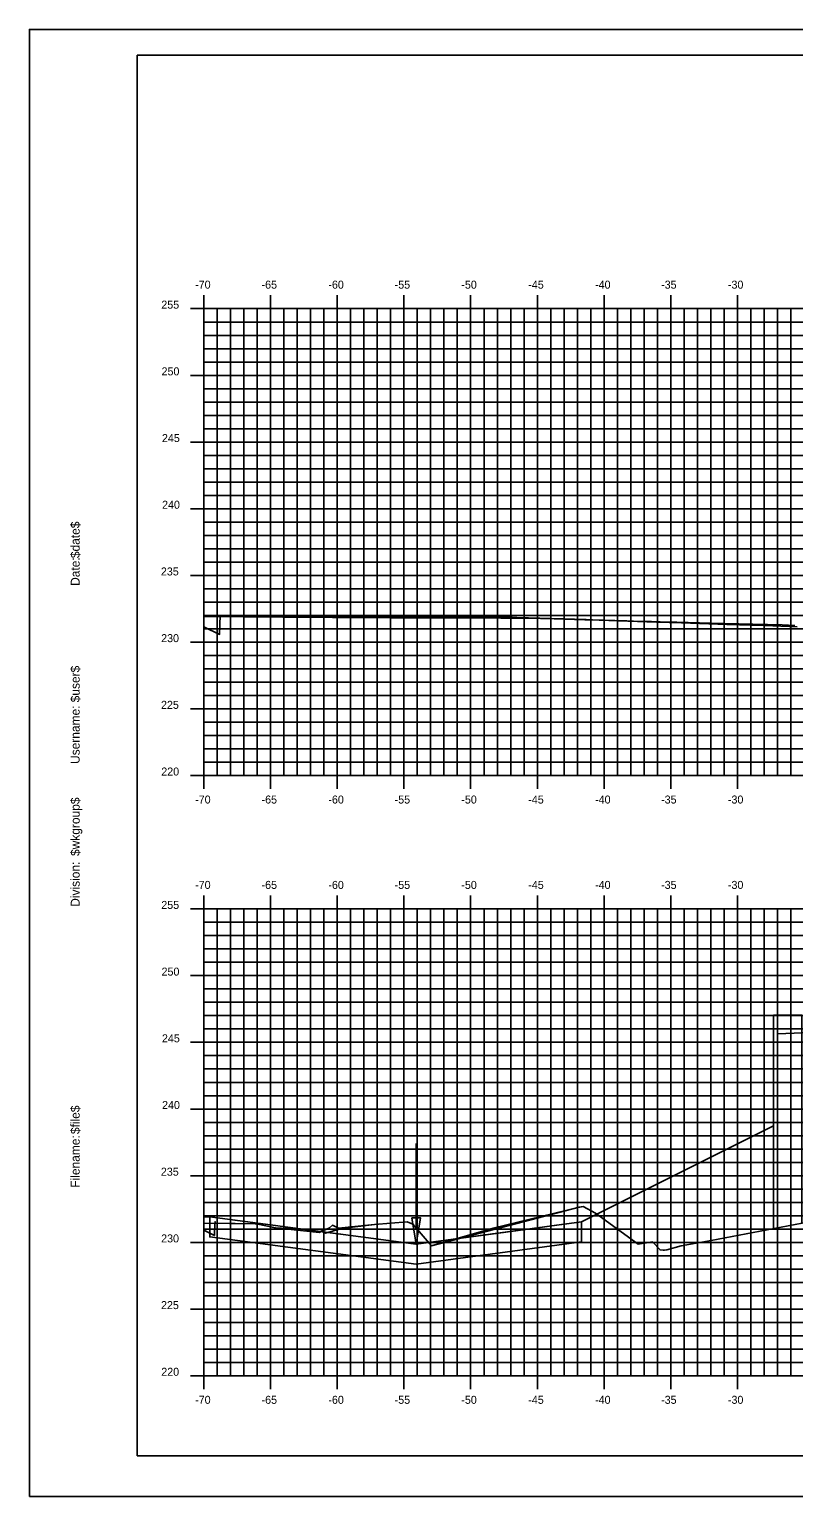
# Model space of a CAD drawing. Extents: x -22 to 1480, y -1511 to 8.
# Drawn here: x 548.6 to 605.9, y -1511.4 to -1401.4 of the extents above; entities that cross this region are included whole.
import ezdxf

# ---------------------------------------------------------------- set-up
doc = ezdxf.new("R2010")
doc.units = 0
for name, color, linetype in [('BORDER', 7, 'Continuous'), ('D_Bridge_Wingwall', 7, 'Continuous'), ('D_Drainage_Ditch_Line', 7, 'Continuous'), ('D_Roadway_Centerline', 7, 'Continuous'), ('D_Roadway_SlopeLines', 7, 'Continuous'), ('H_V ANNOTATION', 7, 'Continuous'), ('MAJOR', 7, 'Continuous'), ('MINOR', 7, 'Continuous'), ('PLOT BOUNDARY', 7, 'Continuous'), ('S_Roadway_Centerline', 7, 'Continuous')]:
    doc.layers.add(name, color=color, linetype=linetype)

msp = doc.modelspace()

# ---------------------------------------------------------------- linework, layer by layer
at = {"layer": 'BORDER'}
for p, q in [((716.67, -1403.33), (556.67, -1403.33)), ((556.67, -1403.33), (556.67, -1508.33)), ((556.67, -1508.33), (716.67, -1508.33))]:
    msp.add_line(p, q, dxfattribs=at)
at = {"layer": 'D_Bridge_Wingwall'}
msp.add_lwpolyline([(606.5, -1490.88), (606.5, -1475.3), (604.38, -1475.3), (604.38, -1491.29)], dxfattribs=at)
at = {"layer": 'D_Drainage_Ditch_Line'}
msp.add_line((577.59, -1491.16), (577.59, -1484.91), dxfattribs=at)
msp.add_lwpolyline([(577.26, -1490.5), (577.92, -1490.5), (577.59, -1492.47)], close=True, dxfattribs=at)
at = {"layer": 'D_Roadway_Centerline'}
for points in [[(561.67, -1445.37), (564, -1445.39), (566.24, -1445.4), (569.27, -1445.42), (572.54, -1445.43), (574.54, -1445.44), (578.84, -1445.45), (579.81, -1445.45), (584.79, -1445.47), (585.07, -1445.48), (585.12, -1445.48), (590.34, -1445.64), (591.3, -1445.68), (595.61, -1445.82), (597.49, -1445.89), (600.88, -1446), (603.7, -1446.09), (606.15, -1446.17)], [(561.67, -1490.41), (561.76, -1490.41), (562.1, -1490.42), (567.03, -1491.07), (569.57, -1491.41), (572.3, -1491.77), (577.55, -1492.46), (577.57, -1492.47), (577.59, -1492.47), (582.84, -1491.75), (586.71, -1491.23), (588.1, -1491.04), (589.98, -1490.78), (604.38, -1483.58)]]:
    msp.add_lwpolyline(points, dxfattribs=at)
at = {"layer": 'D_Roadway_SlopeLines'}
for points in [[(604.69, -1476.7), (619.67, -1476.1), (631.67, -1475.86), (643.67, -1476.1), (662.65, -1476.86)], [(562.1, -1490.42), (577.59, -1492.47)], [(577.59, -1492.47), (589.98, -1490.78)]]:
    msp.add_lwpolyline(points, dxfattribs=at)
msp.add_lwpolyline([(562.1, -1490.42), (577.59, -1492.47), (589.98, -1490.78), (589.98, -1492.28), (577.59, -1493.97), (562.1, -1491.92)], close=True, dxfattribs=at)
at = {"layer": 'MAJOR'}
for p, q in [((561.67, -1421.33), (561.67, -1422.33)), ((566.67, -1421.33), (566.67, -1422.33)), ((571.67, -1421.33), (571.67, -1422.33)), ((576.67, -1421.33), (576.67, -1422.33)), ((581.67, -1421.33), (581.67, -1422.33)), ((586.67, -1421.33), (586.67, -1422.33)), ((591.67, -1421.33), (591.67, -1422.33)), ((596.67, -1421.33), (596.67, -1422.33)), ((601.67, -1421.33), (601.67, -1422.33)), ((560.67, -1422.33), (561.67, -1422.33)), ((561.67, -1422.33), (701.67, -1422.33)), ((561.67, -1457.33), (561.67, -1422.33)), ((561.67, -1457.33), (561.67, -1422.33)), ((561.67, -1422.33), (701.67, -1422.33)), ((566.67, -1457.33), (566.67, -1422.33)), ((571.67, -1457.33), (571.67, -1422.33)), ((576.67, -1457.33), (576.67, -1422.33)), ((581.67, -1457.33), (581.67, -1422.33)), ((586.67, -1457.33), (586.67, -1422.33)), ((591.67, -1457.33), (591.67, -1422.33)), ((596.67, -1457.33), (596.67, -1422.33)), ((601.67, -1457.33), (601.67, -1422.33)), ((560.67, -1427.33), (561.67, -1427.33)), ((561.67, -1427.33), (701.67, -1427.33)), ((560.67, -1432.33), (561.67, -1432.33)), ((561.67, -1432.33), (701.67, -1432.33)), ((560.67, -1437.33), (561.67, -1437.33)), ((561.67, -1437.33), (701.67, -1437.33)), ((560.67, -1442.33), (561.67, -1442.33)), ((561.67, -1442.33), (701.67, -1442.33)), ((560.67, -1447.33), (561.67, -1447.33)), ((561.67, -1447.33), (701.67, -1447.33)), ((560.67, -1452.33), (561.67, -1452.33)), ((561.67, -1452.33), (701.67, -1452.33)), ((560.67, -1457.33), (561.67, -1457.33)), ((561.67, -1457.33), (701.67, -1457.33)), ((561.67, -1457.33), (701.67, -1457.33)), ((561.67, -1458.33), (561.67, -1457.33)), ((566.67, -1458.33), (566.67, -1457.33)), ((571.67, -1458.33), (571.67, -1457.33)), ((576.67, -1458.33), (576.67, -1457.33)), ((581.67, -1458.33), (581.67, -1457.33)), ((586.67, -1458.33), (586.67, -1457.33)), ((591.67, -1458.33), (591.67, -1457.33)), ((596.67, -1458.33), (596.67, -1457.33)), ((601.67, -1458.33), (601.67, -1457.33)), ((560.67, -1467.33), (561.67, -1467.33)), ((561.67, -1466.33), (561.67, -1467.33)), ((561.67, -1467.33), (701.67, -1467.33)), ((561.67, -1502.33), (561.67, -1467.33)), ((561.67, -1502.33), (561.67, -1467.33)), ((561.67, -1467.33), (701.67, -1467.33)), ((566.67, -1466.33), (566.67, -1467.33)), ((566.67, -1502.33), (566.67, -1467.33)), ((571.67, -1466.33), (571.67, -1467.33)), ((571.67, -1502.33), (571.67, -1467.33)), ((576.67, -1466.33), (576.67, -1467.33)), ((576.67, -1502.33), (576.67, -1467.33)), ((581.67, -1466.33), (581.67, -1467.33)), ((581.67, -1502.33), (581.67, -1467.33)), ((586.67, -1466.33), (586.67, -1467.33)), ((586.67, -1502.33), (586.67, -1467.33)), ((591.67, -1466.33), (591.67, -1467.33)), ((591.67, -1502.33), (591.67, -1467.33)), ((596.67, -1466.33), (596.67, -1467.33)), ((596.67, -1502.33), (596.67, -1467.33)), ((601.67, -1466.33), (601.67, -1467.33)), ((601.67, -1502.33), (601.67, -1467.33)), ((560.67, -1472.33), (561.67, -1472.33)), ((561.67, -1472.33), (701.67, -1472.33)), ((560.67, -1477.33), (561.67, -1477.33)), ((561.67, -1477.33), (701.67, -1477.33)), ((560.67, -1482.33), (561.67, -1482.33)), ((561.67, -1482.33), (701.67, -1482.33)), ((560.67, -1487.33), (561.67, -1487.33)), ((561.67, -1487.33), (701.67, -1487.33)), ((560.67, -1492.33), (561.67, -1492.33)), ((561.67, -1492.33), (701.67, -1492.33)), ((560.67, -1497.33), (561.67, -1497.33)), ((561.67, -1497.33), (701.67, -1497.33)), ((560.67, -1502.33), (561.67, -1502.33)), ((561.67, -1502.33), (701.67, -1502.33)), ((561.67, -1502.33), (701.67, -1502.33)), ((561.67, -1503.33), (561.67, -1502.33)), ((566.67, -1503.33), (566.67, -1502.33)), ((571.67, -1503.33), (571.67, -1502.33)), ((576.67, -1503.33), (576.67, -1502.33)), ((581.67, -1503.33), (581.67, -1502.33)), ((586.67, -1503.33), (586.67, -1502.33)), ((591.67, -1503.33), (591.67, -1502.33)), ((596.67, -1503.33), (596.67, -1502.33)), ((601.67, -1503.33), (601.67, -1502.33))]:
    msp.add_line(p, q, dxfattribs=at)
at = {"layer": 'MINOR'}
for p, q in [((561.67, -1423.33), (701.67, -1423.33)), ((561.67, -1423.33), (562.67, -1423.33)), ((562.67, -1457.33), (562.67, -1422.33)), ((563.67, -1457.33), (563.67, -1422.33)), ((564.67, -1457.33), (564.67, -1422.33)), ((565.67, -1457.33), (565.67, -1422.33)), ((567.67, -1457.33), (567.67, -1422.33)), ((568.67, -1457.33), (568.67, -1422.33)), ((569.67, -1457.33), (569.67, -1422.33)), ((570.67, -1457.33), (570.67, -1422.33)), ((572.67, -1457.33), (572.67, -1422.33)), ((573.67, -1457.33), (573.67, -1422.33)), ((574.67, -1457.33), (574.67, -1422.33)), ((575.67, -1457.33), (575.67, -1422.33)), ((577.67, -1457.33), (577.67, -1422.33)), ((578.67, -1457.33), (578.67, -1422.33)), ((579.67, -1457.33), (579.67, -1422.33)), ((580.67, -1457.33), (580.67, -1422.33)), ((582.67, -1457.33), (582.67, -1422.33)), ((583.67, -1457.33), (583.67, -1422.33)), ((584.67, -1457.33), (584.67, -1422.33)), ((585.67, -1457.33), (585.67, -1422.33)), ((587.67, -1457.33), (587.67, -1422.33)), ((588.67, -1457.33), (588.67, -1422.33)), ((589.67, -1457.33), (589.67, -1422.33)), ((590.67, -1457.33), (590.67, -1422.33)), ((592.67, -1457.33), (592.67, -1422.33)), ((593.67, -1457.33), (593.67, -1422.33)), ((594.67, -1457.33), (594.67, -1422.33)), ((595.67, -1457.33), (595.67, -1422.33)), ((597.67, -1457.33), (597.67, -1422.33)), ((598.67, -1457.33), (598.67, -1422.33)), ((599.67, -1457.33), (599.67, -1422.33)), ((600.67, -1457.33), (600.67, -1422.33)), ((602.67, -1457.33), (602.67, -1422.33)), ((603.67, -1457.33), (603.67, -1422.33)), ((604.67, -1457.33), (604.67, -1422.33)), ((605.67, -1457.33), (605.67, -1422.33)), ((561.67, -1424.33), (701.67, -1424.33)), ((561.67, -1424.33), (562.67, -1424.33)), ((561.67, -1425.33), (701.67, -1425.33)), ((561.67, -1425.33), (562.67, -1425.33)), ((561.67, -1426.33), (701.67, -1426.33)), ((561.67, -1426.33), (562.67, -1426.33)), ((561.67, -1428.33), (701.67, -1428.33)), ((561.67, -1428.33), (562.67, -1428.33)), ((561.67, -1429.33), (701.67, -1429.33)), ((561.67, -1429.33), (562.67, -1429.33)), ((561.67, -1430.33), (701.67, -1430.33)), ((561.67, -1430.33), (562.67, -1430.33)), ((561.67, -1431.33), (701.67, -1431.33)), ((561.67, -1431.33), (562.67, -1431.33)), ((561.67, -1433.33), (701.67, -1433.33)), ((561.67, -1433.33), (562.67, -1433.33)), ((561.67, -1434.33), (701.67, -1434.33)), ((561.67, -1434.33), (562.67, -1434.33)), ((561.67, -1435.33), (701.67, -1435.33)), ((561.67, -1435.33), (562.67, -1435.33)), ((561.67, -1436.33), (701.67, -1436.33)), ((561.67, -1436.33), (562.67, -1436.33)), ((561.67, -1438.33), (701.67, -1438.33)), ((561.67, -1438.33), (562.67, -1438.33)), ((561.67, -1439.33), (701.67, -1439.33)), ((561.67, -1439.33), (562.67, -1439.33)), ((561.67, -1440.33), (701.67, -1440.33)), ((561.67, -1440.33), (562.67, -1440.33)), ((561.67, -1441.33), (701.67, -1441.33)), ((561.67, -1441.33), (562.67, -1441.33)), ((561.67, -1443.33), (701.67, -1443.33)), ((561.67, -1443.33), (562.67, -1443.33)), ((561.67, -1444.33), (701.67, -1444.33)), ((561.67, -1444.33), (562.67, -1444.33)), ((561.67, -1445.33), (701.67, -1445.33)), ((561.67, -1445.33), (562.67, -1445.33)), ((561.67, -1446.33), (701.67, -1446.33)), ((561.67, -1446.33), (562.67, -1446.33)), ((561.67, -1448.33), (701.67, -1448.33)), ((561.67, -1448.33), (562.67, -1448.33)), ((561.67, -1449.33), (701.67, -1449.33)), ((561.67, -1449.33), (562.67, -1449.33)), ((561.67, -1450.33), (701.67, -1450.33)), ((561.67, -1450.33), (562.67, -1450.33)), ((561.67, -1451.33), (701.67, -1451.33)), ((561.67, -1451.33), (562.67, -1451.33)), ((561.67, -1453.33), (701.67, -1453.33)), ((561.67, -1453.33), (562.67, -1453.33)), ((561.67, -1454.33), (701.67, -1454.33)), ((561.67, -1454.33), (562.67, -1454.33)), ((561.67, -1455.33), (701.67, -1455.33)), ((561.67, -1455.33), (562.67, -1455.33)), ((561.67, -1456.33), (701.67, -1456.33)), ((561.67, -1456.33), (562.67, -1456.33)), ((562.67, -1502.33), (562.67, -1467.33)), ((563.67, -1502.33), (563.67, -1467.33)), ((564.67, -1502.33), (564.67, -1467.33)), ((565.67, -1502.33), (565.67, -1467.33)), ((567.67, -1502.33), (567.67, -1467.33)), ((568.67, -1502.33), (568.67, -1467.33)), ((569.67, -1502.33), (569.67, -1467.33)), ((570.67, -1502.33), (570.67, -1467.33)), ((572.67, -1502.33), (572.67, -1467.33)), ((573.67, -1502.33), (573.67, -1467.33)), ((574.67, -1502.33), (574.67, -1467.33)), ((575.67, -1502.33), (575.67, -1467.33)), ((577.67, -1502.33), (577.67, -1467.33)), ((578.67, -1502.33), (578.67, -1467.33)), ((579.67, -1502.33), (579.67, -1467.33)), ((580.67, -1502.33), (580.67, -1467.33)), ((582.67, -1502.33), (582.67, -1467.33)), ((583.67, -1502.33), (583.67, -1467.33)), ((584.67, -1502.33), (584.67, -1467.33)), ((585.67, -1502.33), (585.67, -1467.33)), ((587.67, -1502.33), (587.67, -1467.33)), ((588.67, -1502.33), (588.67, -1467.33)), ((589.67, -1502.33), (589.67, -1467.33)), ((590.67, -1502.33), (590.67, -1467.33)), ((592.67, -1502.33), (592.67, -1467.33)), ((593.67, -1502.33), (593.67, -1467.33)), ((594.67, -1502.33), (594.67, -1467.33)), ((595.67, -1502.33), (595.67, -1467.33)), ((597.67, -1502.33), (597.67, -1467.33)), ((598.67, -1502.33), (598.67, -1467.33)), ((599.67, -1502.33), (599.67, -1467.33)), ((600.67, -1502.33), (600.67, -1467.33)), ((602.67, -1502.33), (602.67, -1467.33)), ((603.67, -1502.33), (603.67, -1467.33)), ((604.67, -1502.33), (604.67, -1467.33)), ((605.67, -1502.33), (605.67, -1467.33)), ((561.67, -1468.33), (701.67, -1468.33)), ((561.67, -1468.33), (562.67, -1468.33)), ((561.67, -1469.33), (701.67, -1469.33)), ((561.67, -1469.33), (562.67, -1469.33)), ((561.67, -1470.33), (701.67, -1470.33)), ((561.67, -1470.33), (562.67, -1470.33)), ((561.67, -1471.33), (701.67, -1471.33)), ((561.67, -1471.33), (562.67, -1471.33)), ((561.67, -1473.33), (701.67, -1473.33)), ((561.67, -1473.33), (562.67, -1473.33)), ((561.67, -1474.33), (701.67, -1474.33)), ((561.67, -1474.33), (562.67, -1474.33)), ((561.67, -1475.33), (701.67, -1475.33)), ((561.67, -1475.33), (562.67, -1475.33)), ((561.67, -1476.33), (701.67, -1476.33)), ((561.67, -1476.33), (562.67, -1476.33)), ((561.67, -1478.33), (701.67, -1478.33)), ((561.67, -1478.33), (562.67, -1478.33)), ((561.67, -1479.33), (701.67, -1479.33)), ((561.67, -1479.33), (562.67, -1479.33)), ((561.67, -1480.33), (701.67, -1480.33)), ((561.67, -1480.33), (562.67, -1480.33)), ((561.67, -1481.33), (701.67, -1481.33)), ((561.67, -1481.33), (562.67, -1481.33)), ((561.67, -1483.33), (701.67, -1483.33)), ((561.67, -1483.33), (562.67, -1483.33)), ((561.67, -1484.33), (701.67, -1484.33)), ((561.67, -1484.33), (562.67, -1484.33)), ((561.67, -1485.33), (701.67, -1485.33)), ((561.67, -1485.33), (562.67, -1485.33)), ((561.67, -1486.33), (701.67, -1486.33)), ((561.67, -1486.33), (562.67, -1486.33)), ((561.67, -1488.33), (701.67, -1488.33)), ((561.67, -1488.33), (562.67, -1488.33)), ((561.67, -1489.33), (701.67, -1489.33)), ((561.67, -1489.33), (562.67, -1489.33)), ((561.67, -1490.33), (701.67, -1490.33)), ((561.67, -1490.33), (562.67, -1490.33)), ((561.67, -1491.33), (701.67, -1491.33)), ((561.67, -1491.33), (562.67, -1491.33)), ((561.67, -1493.33), (701.67, -1493.33)), ((561.67, -1493.33), (562.67, -1493.33)), ((561.67, -1494.33), (701.67, -1494.33)), ((561.67, -1494.33), (562.67, -1494.33)), ((561.67, -1495.33), (701.67, -1495.33)), ((561.67, -1495.33), (562.67, -1495.33)), ((561.67, -1496.33), (701.67, -1496.33)), ((561.67, -1496.33), (562.67, -1496.33)), ((561.67, -1498.33), (701.67, -1498.33)), ((561.67, -1498.33), (562.67, -1498.33)), ((561.67, -1499.33), (701.67, -1499.33)), ((561.67, -1499.33), (562.67, -1499.33)), ((561.67, -1500.33), (701.67, -1500.33)), ((561.67, -1500.33), (562.67, -1500.33)), ((561.67, -1501.33), (701.67, -1501.33)), ((561.67, -1501.33), (562.67, -1501.33))]:
    msp.add_line(p, q, dxfattribs=at)
at = {"layer": 'PLOT BOUNDARY'}
msp.add_lwpolyline([(548.58, -1511.39), (718.58, -1511.39), (718.58, -1401.39), (548.58, -1401.39)], close=True, dxfattribs=at)
at = {"layer": 'S_Roadway_Centerline'}
for points in [[(561.67, -1445.41), (561.86, -1445.41), (564.63, -1445.43), (565.21, -1445.44), (565.82, -1445.44), (567.59, -1445.45), (568.17, -1445.46), (569.98, -1445.47), (571.32, -1445.48), (572.37, -1445.48), (574.47, -1445.49), (574.75, -1445.49), (575.62, -1445.5), (577.13, -1445.5), (577.62, -1445.5), (579.52, -1445.51), (580.77, -1445.52), (581.9, -1445.52), (583.92, -1445.53), (584.29, -1445.53), (585.43, -1445.53), (585.88, -1445.54), (586.91, -1445.55), (587.03, -1445.55), (587.07, -1445.56), (587.16, -1445.56), (590.22, -1445.65), (591.61, -1445.68), (593.37, -1445.74), (593.89, -1445.75), (595.23, -1445.79), (596.52, -1445.83), (597.13, -1445.84), (599.67, -1445.91), (601.78, -1445.96), (602.82, -1445.98), (605.04, -1446.03), (605.97, -1446.07)], [(561.67, -1446.17), (562.84, -1446.75), (562.86, -1446.07), (562.86, -1446.06), (562.86, -1446.03), (562.86, -1445.97), (562.86, -1445.94), (562.87, -1445.9), (562.87, -1445.78), (562.87, -1445.78), (562.87, -1445.77), (562.87, -1445.68), (562.88, -1445.66), (562.88, -1445.61), (562.89, -1445.49), (562.89, -1445.42), (564.63, -1445.43), (564.88, -1445.44), (565.21, -1445.44), (565.82, -1445.44), (567.59, -1445.45), (568.17, -1445.46), (569.98, -1445.47), (571.32, -1445.48), (572.37, -1445.48), (574.47, -1445.49), (574.75, -1445.49), (575.62, -1445.5), (577.13, -1445.5), (577.62, -1445.5), (579.52, -1445.51), (580.77, -1445.52), (581.9, -1445.52), (583.92, -1445.53), (584.29, -1445.53), (585.43, -1445.53), (585.88, -1445.54), (586.91, -1445.55), (587.03, -1445.55), (587.07, -1445.56), (587.16, -1445.56), (590.22, -1445.65), (591.61, -1445.68), (593.37, -1445.74), (593.89, -1445.75), (595.23, -1445.79), (596.52, -1445.83), (597.13, -1445.84), (599.67, -1445.91), (601.78, -1445.96), (602.82, -1445.98), (605.04, -1446.03), (605.97, -1446.07)], [(561.67, -1491.41), (562.46, -1491.81), (562.49, -1490.91), (562.5, -1490.86), (562.5, -1490.83), (562.5, -1490.82), (562.5, -1490.82), (562.5, -1490.82), (562.51, -1490.77), (562.51, -1490.9), (565.52, -1490.93), (565.56, -1490.93), (565.56, -1490.93), (565.58, -1490.93), (567.04, -1491.24), (570.31, -1491.58), (570.54, -1491.43), (570.78, -1491.63), (571.99, -1491.3), (574.47, -1490.99), (576.9, -1490.79), (577.33, -1490.96), (578.73, -1492.58), (583.36, -1491.26), (589.72, -1489.71), (590.1, -1489.65), (591.02, -1490.15), (594.24, -1492.45), (595.3, -1492.28), (595.87, -1492.89), (596.1, -1492.92), (596.15, -1492.92), (596.2, -1492.91), (596.39, -1492.89), (597.45, -1492.59), (599.71, -1492.18), (607.06, -1490.78)], [(561.67, -1490.89), (565.52, -1490.93), (565.56, -1490.93), (565.58, -1490.93), (567.04, -1491.24), (569.74, -1491.4), (570.26, -1491.54), (570.31, -1491.58), (571.09, -1491.23), (571.32, -1491.05), (571.77, -1491.26), (574.47, -1490.99), (576.9, -1490.79), (577.33, -1490.96), (578.73, -1492.58), (589.81, -1489.68), (590.1, -1489.65), (591.02, -1490.15), (594.24, -1492.45), (595.3, -1492.28), (595.87, -1492.89), (596.1, -1492.92), (596.15, -1492.92), (596.2, -1492.91), (596.39, -1492.89), (597.45, -1492.59), (599.71, -1492.18), (607.06, -1490.78)]]:
    msp.add_lwpolyline(points, dxfattribs=at)

# ---------------------------------------------------------------- texts
at = {"layer": 'BORDER'}
for s, p in [('$date$', (552.35, -1441.03)), ('Date:', (552.35, -1443.11)), ('$user$', (552.35, -1451.84)), ('Username:', (552.35, -1456.46)), ('$wkgroup$', (552.35, -1463.36)), ('Division:', (552.35, -1467.17)), ('$file$', (552.35, -1484.21)), ('Filename:', (552.35, -1488.23))]:
    msp.add_text(s, height=0.67, rotation=90, dxfattribs=at).set_placement(p)
at = {"layer": 'D_Roadway_Centerline'}
for s, p in [('C', (584.78, -1445.47)), ('L', (584.79, -1445.48))]:
    msp.add_text(s, height=0.0146, dxfattribs=at).set_placement(p)
at = {"layer": 'H_V ANNOTATION'}
for s, p in [('-70', (561.01, -1420.83)), ('-65', (565.99, -1420.83)), ('-60', (571, -1420.83)), ('-55', (575.97, -1420.83)), ('-50', (580.97, -1420.83)), ('-45', (585.99, -1420.83)), ('-40', (591, -1420.83)), ('-35', (595.95, -1420.83)), ('-30', (600.96, -1420.83)), ('255', (558.47, -1422.33)), ('250', (558.49, -1427.33)), ('245', (558.52, -1432.33)), ('240', (558.53, -1437.33)), ('235', (558.44, -1442.33)), ('230', (558.46, -1447.33)), ('225', (558.45, -1452.33)), ('220', (558.47, -1457.33)), ('-70', (561.01, -1459.43)), ('-65', (565.99, -1459.43)), ('-60', (571, -1459.43)), ('-55', (575.97, -1459.43)), ('-50', (580.97, -1459.43)), ('-45', (585.99, -1459.43)), ('-40', (591, -1459.43)), ('-35', (595.95, -1459.43)), ('-30', (600.96, -1459.43)), ('-70', (561.01, -1465.83)), ('-65', (565.99, -1465.83)), ('-60', (571, -1465.83)), ('-55', (575.97, -1465.83)), ('-50', (580.97, -1465.83)), ('-45', (585.99, -1465.83)), ('-40', (591, -1465.83)), ('-35', (595.95, -1465.83)), ('-30', (600.96, -1465.83)), ('255', (558.47, -1467.33)), ('250', (558.49, -1472.33)), ('245', (558.52, -1477.33)), ('240', (558.53, -1482.33)), ('235', (558.44, -1487.33)), ('230', (558.46, -1492.33)), ('225', (558.45, -1497.33)), ('220', (558.47, -1502.33)), ('-70', (561.01, -1504.43)), ('-65', (565.99, -1504.43)), ('-60', (571, -1504.43)), ('-55', (575.97, -1504.43)), ('-50', (580.97, -1504.43)), ('-45', (585.99, -1504.43)), ('-40', (591, -1504.43)), ('-35', (595.95, -1504.43)), ('-30', (600.96, -1504.43))]:
    msp.add_text(s, height=0.6, dxfattribs=at).set_placement(p)

doc.saveas('drawing.dxf')
